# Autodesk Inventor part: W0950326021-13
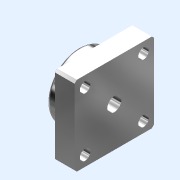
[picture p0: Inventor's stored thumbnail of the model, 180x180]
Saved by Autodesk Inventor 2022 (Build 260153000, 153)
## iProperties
Part Number: W0950326021-13
Material: Generico
Catalog Web Link: www.cadenas.de
Description: COMPENSATION JOINT - MODEL GA-
Vendor: METALWORK
Document SubType Name: Modeling
Designer: partserver
Manufacturer: METALWORK
Mass: 37.3776 g
Surface Area: 104.212 cm^2
Volume: 37.3776 cm^3
Density: 1 g/cm^3
Appearance: Alluminio - Piatto
Category: PARTsolutions
Company: METALWORK
PSOL_IDENT_0: {$CADENAS_DATA\23d-libs\metalwork\actuators\parts\compensation_joint.prj},189 {VTYP=3D},{NB=W0950326
PSOL_IDENT_1: 021-13},{LINA=W0950326021},{NN=COMPENSATION JOINT - MODEL GA},{DATE=18.06.2021 08:06:10},{GEOMDATE=1
PSOL_IDENT_2: 3.11.2009 07:33:00},{VERSION=},{LINEID=110},{WBVAR=},{WBNUMERIC=}  {NB=W0950326021-13},{LINA=W095032
PSOL_IDENT_3: 6021},{KT=DUMMY},{IDNR= },{CODE=W0950326021},{VER=13},{DI=32},{A=49},{B=36},{C=30},{CH=13},{D=11},{D
PSOL_IDENT_4: 1=6.5},{F=M10x1.25},{G=39.5},{G1=17},{P=6.5},{S=12},{S1=10.0},{WG=172},{X=1},{CH1=6.500},{ND=10.000}
PSOL_IDENT_5: ,{P1=1.250}
NB: W0950326021-13
NN: COMPENSATION JOINT - MODEL GA
NBSYN: $CODE.-$VER.
LINA: W0950326021
CATALOG: Metalwork
CODE: W0950326021
VER: 13
DI: 32
A: 49
B: 36
C: 30
CH: 13
D: 11
D1: 6.5
F: M10x1.25
G: 39.5
G1: 17
P: 6.5
S: 12
S1: 10
WG: 172
X: 1
CH1: 6.5
ND: 10
P1: 1.25
SUPPLIER: METALWORK
ARTICLENO: W0950326021-13
BOMINFO: W0950326021
CREATOR: CADENAS GmbH
Title: W0950326021
Author: Cadenas PARTsolutions
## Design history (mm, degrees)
sketch "Sketch_1"
  geometry: L1 (-23.086, 24.5)-(-24.5, 23.086); L2 (-24.5, 23.086)-(-24.5, -23.086); L3 (-24.5, -23.086)-(-23.086, -24.5); L4 (-23.086, -24.5)-(23.086, -24.5); L5 (23.086, -24.5)-(24.5, -23.086); L6 (24.5, -23.086)-(24.5, 23.086); L7 (24.5, 23.086)-(23.086, 24.5); L8 (23.086, 24.5)-(-23.086, 24.5)
  constraints: 16 end point
extrude "Extrusion1" join sketch "Sketch_1" distance "d0" = 12; taper "d1" = 0 deg
sketch "Sketch_2"
  geometry: L1 (12, 0)-(30, 0); L2 (30, 0)-(30, -8.5); L3 (30, -8.5)-(22, -8.5); L4 (22, -8.5)-(22, -17.75); L5 (20, -19.75)-(12, -19.75); L6 (12, -19.75)-(12, 0); L7 (12, 0)-(30, 0); A1 r 2 centre (20, -17.75) between (20, -19.75) and (22, -17.75)
  constraints: 14 end point, 2 point on circle, 1 centre point
revolve "Revolution1" sketch "Sketch_2" stored, may be unused: angle "d2" = 360 deg
sketch "Sketch_3"
  geometry: L1 (-13, -13)-(13, -13); L2 (13, -13)-(13, 13); L3 (13, 13)-(-13, 13); L4 (-13, 13)-(-13, -13); L5 (-6.5, -6.5)-(6.5, -6.5); L6 (6.5, -6.5)-(6.5, 6.5); L7 (6.5, 6.5)-(-6.5, 6.5); L8 (-6.5, 6.5)-(-6.5, -6.5)
  constraints: 16 end point
extrude "Extrusion2" cut sketch "Sketch_3" distance "d3" = 6.5; taper "d4" = 0 deg
sketch "Sketch4"
  geometry: 1 further point
hole "Hole1" sketch "Sketch4" at (-18, -18) diameter "d5" = 6.5; stored, may be unused: countersink angle "d9" = 90 deg, drill point angle "d11" = 0 deg; dims "d6" = 6, "d7" = 11, "d8" = 6.5, "d10" = 12
pattern_linear "Rectangular Pattern1" dims "d14" = 36, "d17" = 36
sketch "Sketch5"
  geometry: 1 further point
hole "Hole2" sketch "Sketch5" at (-6.5, 5.477) diameter "d18" = 8.647; stored, may be unused: countersink angle "d22" = 90 deg, drill point angle "d24" = 0 deg; dims "d19" = 18, "d20" = 4, "d21" = 2, "d23" = 30
node "body_XY"
node "body_YZ"
node "body_ZX"
node "body_X"
node "body_Y"
node "body_Z"
node "body_Center"
node "rod_ip_XY"
node "rod_ip_YZ"
node "rod_ip_ZX"
node "rod_ip_X"
node "rod_ip_Y"
node "rod_ip_Z"
node "rod_ip_Center"
node "screws_1_XY"
node "screws_1_YZ"
node "screws_1_ZX"
node "screws_1_X"
node "screws_1_Y"
node "screws_1_Z"
node "screws_1_Center"
node "screws_2_XY"
node "screws_2_YZ"
node "screws_2_ZX"
node "screws_2_X"
node "screws_2_Y"
node "screws_2_Z"
node "screws_2_Center"
node "screws_3_XY"
node "screws_3_YZ"
node "screws_3_ZX"
node "screws_3_X"
node "screws_3_Y"
node "screws_3_Z"
node "screws_3_Center"
node "screws_4_XY"
node "screws_4_YZ"
node "screws_4_ZX"
node "screws_4_X"
node "screws_4_Y"
node "screws_4_Z"
node "screws_4_Center"
body "Solid1"
other parameters: "d25" = 0, "d26" = 0, "d27" = 0, "d28" = 0, "d29" = 0, "d30" = 0
